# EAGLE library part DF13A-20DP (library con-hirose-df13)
DF13-20DP Double row, 1.25mm Pitch Miniature Crimping Connector.
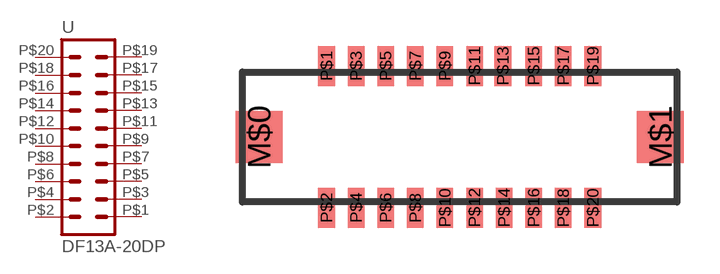
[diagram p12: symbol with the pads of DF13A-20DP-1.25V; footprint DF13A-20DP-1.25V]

Designator prefix -

## DF13A-20DP20DP-1.25V  [DF13A-20DP-1.25V]
P$1  1  pas
P$2  2  pas
P$3  3  pas
P$4  4  pas
P$5  5  pas
P$6  6  pas
P$7  7  pas
P$8  8  pas
P$9  9  pas
P$10  10  pas
P$11  11  pas
P$12  12  pas
P$13  13  pas
P$14  14  pas
P$15  15  pas
P$16  16  pas
P$17  17  pas
P$18  18  pas
P$19  19  pas
P$20  20  pas

## Footprint DF13A-20DP-1.25V (pad centres in mm)
Double Row Straight Pin Header (SMT)
smd 2 x 2.2: M$0 -8.475,0; M$1 8.475,0
smd 0.7 x 1.7: P$1 -5.625,3; P$2 -5.625,-3; P$3 -4.375,3; P$4 -4.375,-3; P$5 -3.125,3; P$6 -3.125,-3; P$7 -1.875,3; P$8 -1.875,-3; P$9 -0.625,3; P$10 -0.625,-3; P$11 0.625,3; P$12 0.625,-3; P$13 1.825,3; P$14 1.875,-3; P$15 3.125,3; P$16 3.125,-3; P$17 4.375,3; P$18 4.375,-3; P$19 5.625,3; P$20 5.625,-3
